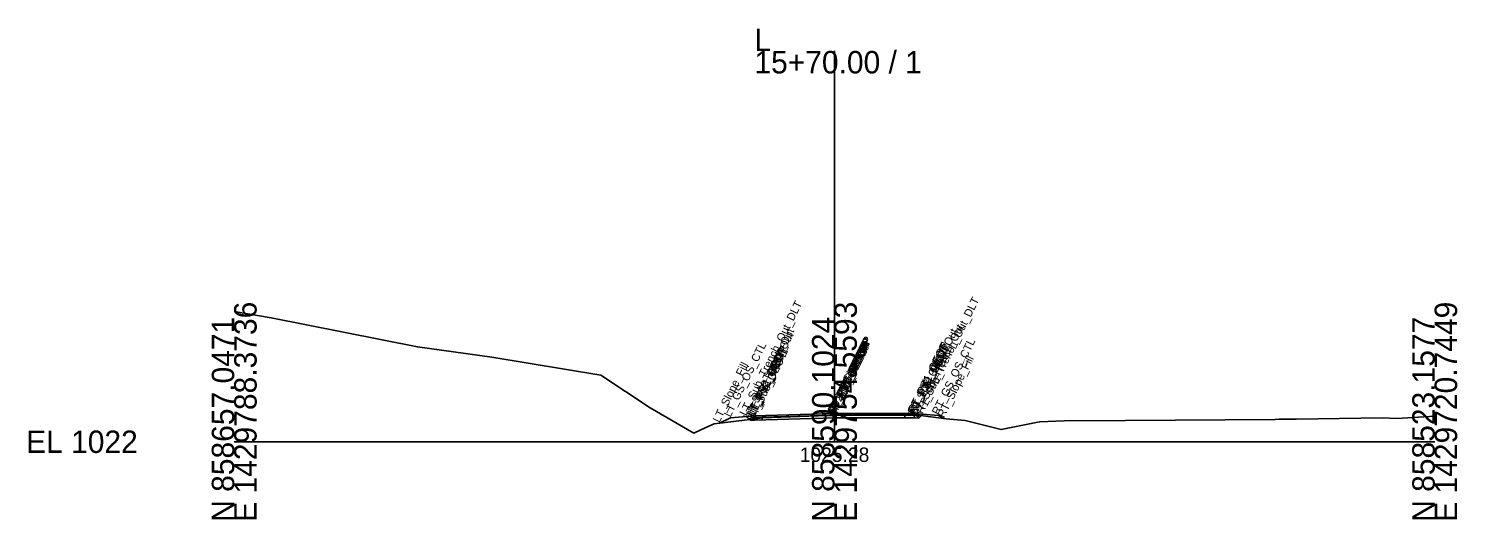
# Model space of a CAD drawing. Extents: x -26 to 2303, y -10 to 19558.
# Drawn here: x 2124.3 to 2302.8, y 7990.3 to 8051.6 of the extents above; entities that cross this region are included whole.
import ezdxf

# ---------------------------------------------------------------- set-up
doc = ezdxf.new("R2010")
doc.units = 0
for name, color, linetype in [('Default', 7, 'Continuous'), ('Exist CMT Pavement', 7, 'Continuous'), ('Exist Cross Section Cell', 7, 'Continuous'), ('Exist XS Center Line Elevation Label', 7, 'Continuous'), ('Exist XS Ground Line', 7, 'Continuous'), ('Prop CMT Conc Surface', 7, 'Continuous'), ('Prop CMT Pvmt Course 1', 7, 'Continuous'), ('Prop CMT Pvmt Course 2', 7, 'Continuous'), ('Prop CMT Pvmt Surface', 7, 'Continuous'), ('Prop CMT Pvmt Surface Shoulder', 7, 'Continuous'), ('Prop CMT Shld Paved Course 1', 7, 'Continuous'), ('Prop CMT Shld Paved Course 2', 7, 'Continuous'), ('Prop CMT Slope Grass', 7, 'Continuous'), ('Prop CMT Subgrade Earthwork', 7, 'Continuous'), ('Prop XS Dump Level', 7, 'Continuous')]:
    doc.layers.add(name, color=color, linetype=linetype)

msp = doc.modelspace()

# ---------------------------------------------------------------- linework, layer by layer
at = {"layer": 'Exist CMT Pavement'}
for p, q in [((2225, 8003.32), (2215.95, 8003.06)), ((2215.95, 8003.06), (2215.95, 8002.97)), ((2226.35, 8003.32), (2225, 8003.32))]:
    msp.add_line(p, q, dxfattribs=at)
msp.add_lwpolyline([(2215.95, 8002.97), (2224.15, 8003.26), (2224.71, 8003.27), (2226.35, 8003.32)], dxfattribs=at)
at = {"layer": 'Exist Cross Section Cell'}
for p, q in [((2225, 8000), (2225, 8048.78)), ((2150, 8000), (2225, 8000)), ((2225, 8000), (2300, 8000))]:
    msp.add_line(p, q, dxfattribs=at)
at = {"layer": 'Exist XS Ground Line'}
msp.add_lwpolyline([(2150, 8016.26), (2154.6, 8015.46), (2172.89, 8011.84), (2182.21, 8010.56), (2195.83, 8008.31), (2201.99, 8004.25), (2207.43, 8001.09), (2208.92, 8001.79), (2209.97, 8002.23), (2215.15, 8002.87), (2215.95, 8002.97), (2224.15, 8003.26), (2224.71, 8003.27), (2233.4, 8003.51), (2233.79, 8003.51), (2234.48, 8003.45), (2235.11, 8003.38), (2238.96, 8002.88), (2241.33, 8002.66), (2244.83, 8001.77), (2245.82, 8001.51), (2249.77, 8002.34), (2250.63, 8002.5), (2253.7, 8002.62), (2261.38, 8002.65), (2280.06, 8002.79), (2280.51, 8002.81), (2282.68, 8002.8), (2293.49, 8002.97), (2295.25, 8002.91), (2300, 8003.19)], dxfattribs=at)
at = {"layer": 'Prop CMT Conc Surface'}
for p, q in [((2215.95, 8002.72), (2215.95, 8003.06)), ((2233.79, 8003.51), (2233.79, 8002.97))]:
    msp.add_line(p, q, dxfattribs=at)
at = {"layer": 'Prop CMT Pvmt Course 1'}
for points in [[(2225, 8003.53), (2215, 8003.24)], [(2215, 8003.03), (2225, 8003.32)], [(2215, 8003.24), (2215, 8003.03)], [(2225, 8003.32), (2225, 8003.53)], [(2225, 8003.53), (2235, 8003.51)], [(2225, 8003.32), (2225, 8003.53)], [(2235, 8003.3), (2225, 8003.32)], [(2235, 8003.51), (2235, 8003.3)]]:
    msp.add_lwpolyline(points, dxfattribs=at)
msp.add_lwpolyline([(2225, 8003.32), (2225, 8003.4), (2225, 8003.4), (2225, 8003.32)], close=True, dxfattribs=at)
msp.add_lwpolyline([(2225, 8003.32), (2225, 8003.4), (2225, 8003.4), (2225, 8003.32)], close=True, dxfattribs=at)
at = {"layer": 'Prop CMT Pvmt Course 2'}
for points in [[(2225, 8003.32), (2215, 8003.03)], [(2215, 8003.03), (2215, 8002.69)], [(2215, 8002.69), (2215.95, 8002.72)], [(2225, 8003.32), (2235, 8003.3)], [(2235, 8002.97), (2233.79, 8002.97)], [(2235, 8003.3), (2235, 8002.97)]]:
    msp.add_lwpolyline(points, dxfattribs=at)
at = {"layer": 'Prop CMT Pvmt Surface'}
for points in [[(2225, 8003.53), (2215, 8003.24)], [(2225, 8003.53), (2235, 8003.51)]]:
    msp.add_lwpolyline(points, dxfattribs=at)
at = {"layer": 'Prop CMT Pvmt Surface Shoulder'}
for points in [[(2215, 8003.24), (2215, 8003.24)], [(2235, 8003.51), (2235, 8003.51)]]:
    msp.add_lwpolyline(points, dxfattribs=at)
at = {"layer": 'Prop CMT Shld Paved Course 1'}
for points in [[(2215, 8003.24), (2214.79, 8003.02)], [(2214.79, 8003.02), (2215, 8003.03)], [(2215, 8003.24), (2215, 8003.24)], [(2215, 8003.03), (2215, 8003.24)], [(2235, 8003.51), (2235, 8003.51)], [(2235, 8003.51), (2235.21, 8003.29)], [(2235, 8003.3), (2235, 8003.51)], [(2235.21, 8003.29), (2235, 8003.3)]]:
    msp.add_lwpolyline(points, dxfattribs=at)
at = {"layer": 'Prop CMT Shld Paved Course 2'}
for points in [[(2214.79, 8003.02), (2214.45, 8002.68)], [(2214.45, 8002.68), (2215, 8002.69)], [(2215, 8003.03), (2214.79, 8003.02)], [(2214.79, 8003.02), (2214.79, 8003.02)], [(2215, 8002.69), (2215, 8003.03)], [(2235, 8003.3), (2235.21, 8003.29)], [(2235, 8002.97), (2235, 8003.3)], [(2235.55, 8002.95), (2235, 8002.97)], [(2235.21, 8003.29), (2235.21, 8003.29)], [(2235.21, 8003.29), (2235.55, 8002.95)]]:
    msp.add_lwpolyline(points, dxfattribs=at)
at = {"layer": 'Prop CMT Slope Grass'}
for points in [[(2215, 8003.24), (2212, 8003), (2210.63, 8002.31)], [(2235, 8003.51), (2238, 8003.27), (2238.71, 8002.91)]]:
    msp.add_lwpolyline(points, dxfattribs=at)
at = {"layer": 'Prop CMT Subgrade Earthwork'}
for points in [[(2214.45, 8002.68), (2213.98, 8003.15)], [(2215, 8002.69), (2214.45, 8002.68)], [(2225, 8002.99), (2215, 8002.69)], [(2225, 8002.99), (2235, 8002.97)], [(2235, 8002.97), (2235.55, 8002.95)], [(2235.55, 8002.95), (2236.02, 8003.42)]]:
    msp.add_lwpolyline(points, dxfattribs=at)

# ---------------------------------------------------------------- texts
at = {"layer": 'Default'}
msp.add_text('-', height=0.0001, dxfattribs=at).set_placement((2150, 8000))
at = {"layer": 'Exist Cross Section Cell'}
for s, p in [('L', (2215, 8048.78)), ('15+70.00 / 1', (2215, 8045.98)), ('EL 1022', (2124, 7998.6))]:
    msp.add_text(s, height=2.8, dxfattribs=at).set_placement(p)
for s, p in [('E 1429788.3736', (2152.8, 7990)), ('E 1429754.5593', (2227.8, 7990)), ('E 1429720.7449', (2302.8, 7990)), ('N 858657.0471', (2150, 7990)), ('N 858590.1024', (2225, 7990)), ('N 858523.1577', (2300, 7990))]:
    msp.add_text(s, height=2.8, rotation=90, dxfattribs=at).set_placement(p)
at = {"layer": 'Exist XS Center Line Elevation Label'}
msp.add_text('1025.28', height=1.8, dxfattribs=at).set_placement((2220.66, 7997.48))
at = {"layer": 'Prop XS Dump Level'}
for s, p in [('RT_Sub_Trench_Out_DLT', (2236.02, 8003.42)), ('LT_Sub_Trench_Out_DLT', (2213.98, 8003.15)), ('RT_Sub_Trench_Out', (2235.55, 8002.95)), ('LT_Sub_Trench_Out', (2214.45, 8002.68)), ('LT_PS2_Shelf_Out', (2214.79, 8003.02)), ('RT_PV1_OEEOP', (2225, 8003.4)), ('RT_PV2_OEEOP', (2225, 8003.32)), ('LT_PV1_OEEOP', (2225, 8003.4)), ('LT_PV2_OEEOP', (2225, 8003.32)), ('RT_Sub_OEEOP', (2225, 8002.99)), ('RT_PV1_IEEOP', (2225, 8003.4)), ('RT_PS2_Shelf_Out', (2235.21, 8003.29)), ('RT_GS_OS_CTL', (2238, 8003.27)), ('LT_GS_OS_CTL', (2212, 8003)), ('LT_PS2_OEOP', (2214.79, 8003.02)), ('LT_PV1_OEOT', (2215, 8003.24)), ('LT_PS1_OEOP', (2215, 8003.24)), ('LT_PV2_OEOT', (2215, 8003.03)), ('LT_Sub_OEOT', (2215, 8002.69)), ('RT_PV2_IEEOP', (2225, 8003.32)), ('LT_Sub_OEEOP', (2225, 8002.99)), ('LT_PV1_IEEOP', (2225, 8003.4)), ('LT_PV2_IEEOP', (2225, 8003.32)), ('RT_PV1_OEOT', (2235, 8003.51)), ('RT_PS1_OEOP', (2235, 8003.51)), ('RT_PV2_OEOT', (2235, 8003.3)), ('RT_Sub_OEOT', (2235, 8002.97)), ('RT_PS2_OEOP', (2235.21, 8003.29)), ('RT_Slope_Fill', (2238.71, 8002.91)), ('LT_Slope_Fill', (2210.63, 8002.31)), ('PV1_PGL', (2225, 8003.53)), ('PV2_PGL', (2225, 8003.32))]:
    msp.add_text(s, height=1, rotation=63.5833, dxfattribs=at).set_placement(p)

doc.saveas('drawing.dxf')
